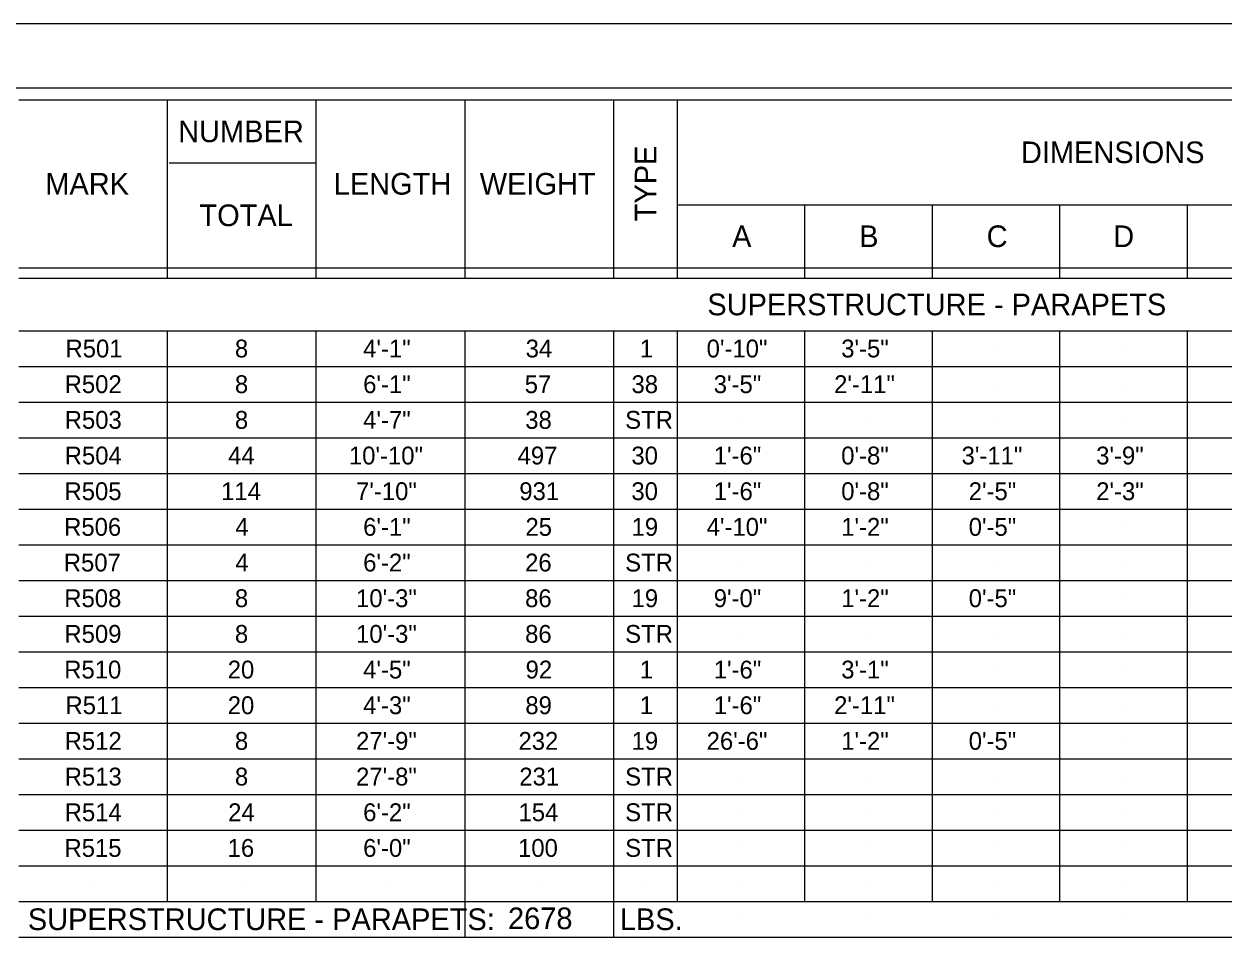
# Model space of a CAD drawing. Extents: x 0 to 34, y 0 to 22.
# Drawn here: x 16.8 to 26.21, y 14.76 to 22 of the extents above; entities that cross this region are included whole.
import ezdxf

# ---------------------------------------------------------------- set-up
doc = ezdxf.new("R2010")
doc.units = 0
for name, color, linetype in [('BR_P_Gen_Text', 7, 'Continuous'), ('SH_Border', 7, 'Continuous'), ('SH_Cut_Line', 7, 'Continuous')]:
    doc.layers.add(name, color=color, linetype=linetype)

msp = doc.modelspace()

# ---------------------------------------------------------------- linework, layer by layer
at = {"layer": 'BR_P_Gen_Text'}
for p, q in [((16.7602, 21.4043), (31.927, 21.4044)), ((17.9269, 20.0043), (17.9269, 21.4043)), ((19.0936, 20.0041), (19.0936, 21.4043)), ((20.2602, 20.0043), (20.2603, 21.4043)), ((21.427, 20.0044), (21.427, 21.4043)), ((21.927, 20.0044), (21.927, 21.4043)), ((17.9406, 20.9102), (19.0936, 20.9102)), ((21.927, 20.5808), (28.927, 20.5809)), ((22.927, 20.0042), (22.927, 20.5808)), ((23.927, 20.0042), (23.927, 20.5808)), ((24.927, 20.0041), (24.927, 20.5809)), ((25.927, 20.0042), (25.927, 20.5809)), ((16.7602, 20.0866), (31.927, 20.0867)), ((16.7602, 20.0043), (31.927, 20.0043)), ((22.8436, 19.7984), (22.8436, 19.7984)), ((16.7602, 19.5926), (31.927, 19.5927)), ((17.9268, 15.1126), (17.9269, 19.5926)), ((19.0936, 15.1126), (19.0936, 19.5926)), ((20.2603, 14.8327), (20.2602, 19.5926)), ((21.427, 14.8327), (21.427, 19.5927)), ((21.927, 15.1126), (21.927, 19.5927)), ((22.9269, 15.1126), (22.927, 19.5926)), ((23.927, 15.1126), (23.927, 19.5926)), ((24.927, 15.1126), (24.927, 19.5926)), ((25.927, 15.1126), (25.927, 19.5926)), ((17.3435, 19.4526), (17.3435, 19.4526)), ((18.5102, 19.4526), (18.5102, 19.4526)), ((19.6769, 19.4526), (19.6769, 19.4526)), ((20.8437, 19.4527), (20.8437, 19.4527)), ((21.677, 19.4526), (21.677, 19.4526)), ((22.427, 19.4526), (22.427, 19.4526)), ((23.427, 19.4526), (23.427, 19.4526)), ((24.427, 19.4526), (24.427, 19.4526)), ((25.427, 19.4526), (25.427, 19.4526)), ((16.7602, 19.3126), (31.927, 19.3126)), ((17.3435, 19.1726), (17.3435, 19.1726)), ((18.5102, 19.1726), (18.5102, 19.1726)), ((19.6769, 19.1726), (19.6769, 19.1726)), ((20.8437, 19.1727), (20.8437, 19.1727)), ((21.677, 19.1726), (21.677, 19.1726)), ((22.427, 19.1726), (22.427, 19.1726)), ((23.427, 19.1726), (23.427, 19.1726)), ((23.427, 19.1726), (23.427, 19.1726)), ((24.427, 19.1726), (24.427, 19.1726)), ((25.427, 19.1726), (25.427, 19.1726)), ((16.7602, 19.0326), (31.927, 19.0326)), ((17.3435, 18.8926), (17.3435, 18.8926)), ((18.5102, 18.8926), (18.5102, 18.8926)), ((19.6769, 18.8926), (19.6769, 18.8926)), ((20.8437, 18.8927), (20.8437, 18.8927)), ((21.677, 18.8926), (21.677, 18.8926)), ((22.427, 18.8926), (22.427, 18.8926)), ((23.427, 18.8926), (23.427, 18.8926)), ((24.427, 18.8926), (24.427, 18.8926)), ((25.427, 18.8926), (25.427, 18.8926)), ((16.7602, 18.7526), (31.927, 18.7526)), ((17.3435, 18.6126), (17.3435, 18.6126)), ((17.3435, 18.6126), (17.3435, 18.6126)), ((22.427, 18.6126), (22.427, 18.6126)), ((23.427, 18.6126), (23.427, 18.6126)), ((24.427, 18.6126), (24.427, 18.6126)), ((25.427, 18.6126), (25.427, 18.6126)), ((16.7602, 18.4726), (31.927, 18.4726)), ((17.3435, 18.3326), (17.3435, 18.3326)), ((18.5102, 18.3326), (18.5102, 18.3326)), ((19.6769, 18.3326), (19.6769, 18.3326)), ((20.8437, 18.3327), (20.8437, 18.3327)), ((21.677, 18.3326), (21.677, 18.3326)), ((22.427, 18.3326), (22.427, 18.3326)), ((23.427, 18.3326), (23.427, 18.3326)), ((24.427, 18.3326), (24.427, 18.3326)), ((25.427, 18.3326), (25.427, 18.3326)), ((16.7602, 18.1926), (31.927, 18.1926)), ((17.3435, 18.0526), (17.3435, 18.0526)), ((18.5102, 18.0526), (18.5102, 18.0526)), ((19.6769, 18.0526), (19.6769, 18.0526)), ((20.8437, 18.0527), (20.8437, 18.0527)), ((21.677, 18.0526), (21.677, 18.0526)), ((22.427, 18.0526), (22.427, 18.0526)), ((23.427, 18.0526), (23.427, 18.0526)), ((24.427, 18.0526), (24.427, 18.0526)), ((25.427, 18.0526), (25.427, 18.0526)), ((16.7602, 17.9126), (31.927, 17.9127)), ((17.3435, 17.7726), (17.3435, 17.7726)), ((18.5102, 17.7726), (18.5102, 17.7726)), ((19.6769, 17.7726), (19.6769, 17.7726)), ((20.8437, 17.7727), (20.8437, 17.7727)), ((21.677, 17.7726), (21.677, 17.7726)), ((22.427, 17.7726), (22.427, 17.7726)), ((23.427, 17.7726), (23.427, 17.7726)), ((24.427, 17.7726), (24.427, 17.7726)), ((25.427, 17.7726), (25.427, 17.7726)), ((16.7602, 17.6326), (31.927, 17.6327)), ((17.3435, 17.4926), (17.3435, 17.4926)), ((17.3435, 17.4926), (17.3435, 17.4926)), ((18.5102, 17.4926), (18.5102, 17.4926)), ((18.5102, 17.4926), (18.5102, 17.4926)), ((19.6769, 17.4926), (19.6769, 17.4926)), ((19.6769, 17.4926), (19.6769, 17.4926)), ((20.8437, 17.4927), (20.8437, 17.4927)), ((20.8437, 17.4927), (20.8437, 17.4927)), ((21.677, 17.4926), (21.677, 17.4926)), ((21.677, 17.4926), (21.677, 17.4926)), ((22.427, 17.4926), (22.427, 17.4926)), ((22.427, 17.4926), (22.427, 17.4926)), ((23.427, 17.4926), (23.427, 17.4926)), ((23.427, 17.4926), (23.427, 17.4926)), ((24.427, 17.4926), (24.427, 17.4926)), ((24.427, 17.4926), (24.427, 17.4926)), ((25.427, 17.4926), (25.427, 17.4926)), ((25.427, 17.4926), (25.427, 17.4926)), ((16.7602, 17.3526), (31.927, 17.3527)), ((17.3435, 17.2126), (17.3435, 17.2126)), ((17.3435, 17.2126), (17.3435, 17.2126)), ((18.5102, 17.2126), (18.5102, 17.2126)), ((18.5102, 17.2126), (18.5102, 17.2126)), ((19.6769, 17.2126), (19.6769, 17.2126)), ((19.6769, 17.2126), (19.6769, 17.2126)), ((20.8437, 17.2127), (20.8437, 17.2127)), ((20.8437, 17.2127), (20.8437, 17.2127)), ((21.677, 17.2126), (21.677, 17.2126)), ((21.677, 17.2126), (21.677, 17.2126)), ((22.427, 17.2126), (22.427, 17.2126)), ((22.427, 17.2126), (22.427, 17.2126)), ((23.427, 17.2126), (23.427, 17.2126)), ((23.427, 17.2126), (23.427, 17.2126)), ((24.427, 17.2126), (24.427, 17.2126)), ((24.427, 17.2126), (24.427, 17.2126)), ((25.427, 17.2126), (25.427, 17.2126)), ((25.427, 17.2126), (25.427, 17.2126)), ((16.7602, 17.0726), (31.927, 17.0727)), ((17.3435, 16.9326), (17.3435, 16.9326)), ((18.5102, 16.9326), (18.5102, 16.9326)), ((19.6769, 16.9326), (19.6769, 16.9326)), ((20.8437, 16.9327), (20.8437, 16.9327)), ((21.677, 16.9326), (21.677, 16.9326)), ((22.427, 16.9326), (22.427, 16.9326)), ((23.427, 16.9326), (23.427, 16.9326)), ((24.427, 16.9326), (24.427, 16.9326)), ((25.427, 16.9326), (25.427, 16.9326)), ((16.7602, 16.7926), (31.927, 16.7926)), ((17.3435, 16.6526), (17.3435, 16.6526)), ((18.5102, 16.6526), (18.5102, 16.6526)), ((19.6769, 16.6526), (19.6769, 16.6526)), ((20.8437, 16.6527), (20.8437, 16.6527)), ((21.677, 16.6526), (21.677, 16.6526)), ((22.427, 16.6526), (22.427, 16.6526)), ((23.427, 16.6526), (23.427, 16.6526)), ((24.427, 16.6526), (24.427, 16.6526)), ((25.427, 16.6526), (25.427, 16.6526)), ((16.7602, 16.5126), (31.927, 16.5126)), ((17.3435, 16.3726), (17.3435, 16.3726)), ((18.5102, 16.3726), (18.5102, 16.3726)), ((19.6769, 16.3726), (19.6769, 16.3726)), ((20.8437, 16.3727), (20.8437, 16.3727)), ((21.677, 16.3726), (21.677, 16.3726)), ((22.427, 16.3726), (22.427, 16.3726)), ((23.427, 16.3726), (23.427, 16.3726)), ((24.427, 16.3726), (24.427, 16.3726)), ((25.427, 16.3726), (25.427, 16.3726)), ((16.7602, 16.2326), (31.927, 16.2326)), ((17.3435, 16.0926), (17.3435, 16.0926)), ((18.5102, 16.0926), (18.5102, 16.0926)), ((19.6769, 16.0926), (19.6769, 16.0926)), ((20.8437, 16.0927), (20.8437, 16.0927)), ((21.677, 16.0926), (21.677, 16.0926)), ((22.427, 16.0926), (22.427, 16.0926)), ((23.427, 16.0926), (23.427, 16.0926)), ((24.427, 16.0926), (24.427, 16.0926)), ((25.427, 16.0926), (25.427, 16.0926)), ((16.7602, 15.9526), (31.927, 15.9526)), ((17.3435, 15.8126), (17.3435, 15.8126)), ((18.5102, 15.8126), (18.5102, 15.8126)), ((19.6769, 15.8126), (19.6769, 15.8126)), ((20.8437, 15.8127), (20.8437, 15.8127)), ((21.677, 15.8126), (21.677, 15.8126)), ((22.427, 15.8126), (22.427, 15.8126)), ((23.427, 15.8126), (23.427, 15.8126)), ((24.427, 15.8126), (24.427, 15.8126)), ((25.427, 15.8126), (25.427, 15.8126)), ((16.7602, 15.6726), (31.927, 15.6726)), ((17.3435, 15.5326), (17.3435, 15.5326)), ((18.5102, 15.5326), (18.5102, 15.5326)), ((19.6769, 15.5326), (19.6769, 15.5326)), ((20.8437, 15.5327), (20.8437, 15.5327)), ((21.677, 15.5326), (21.677, 15.5326)), ((22.427, 15.5326), (22.427, 15.5326)), ((23.427, 15.5326), (23.427, 15.5326)), ((24.427, 15.5326), (24.427, 15.5326)), ((25.427, 15.5326), (25.427, 15.5326)), ((16.7602, 15.3926), (31.927, 15.3926)), ((17.3435, 15.2526), (17.3435, 15.2526)), ((18.5102, 15.2526), (18.5102, 15.2526)), ((19.6769, 15.2526), (19.6769, 15.2526)), ((20.8437, 15.2527), (20.8437, 15.2527)), ((21.677, 15.2526), (21.677, 15.2526)), ((22.427, 15.2526), (22.427, 15.2526)), ((23.427, 15.2526), (23.427, 15.2526)), ((24.427, 15.2526), (24.427, 15.2526)), ((25.427, 15.2526), (25.427, 15.2526)), ((16.7602, 15.1126), (31.927, 15.1126)), ((17.3435, 14.9726), (17.3435, 14.9726)), ((18.5102, 14.9726), (18.5102, 14.9726)), ((19.6769, 14.9726), (19.6769, 14.9726)), ((20.8437, 14.9727), (20.8437, 14.9727)), ((21.677, 14.9726), (21.677, 14.9726)), ((22.427, 14.9726), (22.427, 14.9726)), ((23.427, 14.9726), (23.427, 14.9726)), ((24.427, 14.9726), (24.427, 14.9726)), ((25.427, 14.9726), (25.427, 14.9726)), ((16.7602, 14.8327), (31.927, 14.8327))]:
    msp.add_line(p, q, dxfattribs=at)
at = {"layer": 'SH_Border'}
msp.add_lwpolyline([(1.5, 21.5), (33.5, 21.5), (33.5, 0.5), (1.5, 0.5)], close=True, dxfattribs=at)
at = {"layer": 'SH_Cut_Line'}
msp.add_lwpolyline([(0, 0), (34, 0), (34, 22), (0, 22)], close=True, dxfattribs=at)

# ---------------------------------------------------------------- texts
at = {"layer": 'BR_P_Gen_Text'}
for s, height, p in [('NUMBER', 0.17, (18.0101, 21.0722)), ('DIMENSIONS', 0.17, (24.6212, 20.9076)), ('MARK', 0.17, (16.9678, 20.6605)), ('LENGTH', 0.17, (19.2303, 20.6605)), ('WEIGHT', 0.17, (20.3758, 20.6605)), ('TOTAL', 0.17, (18.1771, 20.4134)), ('A', 0.17, (22.3553, 20.2488)), ('B', 0.17, (23.3522, 20.2488)), ('C', 0.17, (24.3522, 20.2488)), ('D', 0.17, (25.3449, 20.2488)), ('SUPERSTRUCTURE - PARAPETS', 0.17, (22.1609, 19.7135)), ('R501', 0.14, (17.1261, 19.3826)), ('8', 0.14, (18.4552, 19.3826)), ('4\'-1"', 0.14, (19.4613, 19.3826)), ('34', 0.14, (20.7359, 19.3826)), ('1', 0.14, (21.6311, 19.3826)), ('0\'-10"', 0.14, (22.1555, 19.3826)), ('3\'-5"', 0.14, (23.2113, 19.3826)), ('R502', 0.14, (17.1197, 19.1026)), ('8', 0.14, (18.4552, 19.1026)), ('6\'-1"', 0.14, (19.4613, 19.1026)), ('57', 0.14, (20.7287, 19.1026)), ('38', 0.14, (21.5661, 19.1026)), ('3\'-5"', 0.14, (22.2113, 19.1026)), ('2\'-11"', 0.14, (23.1555, 19.1026)), ('R503', 0.14, (17.1201, 18.8226)), ('8', 0.14, (18.4552, 18.8226)), ('4\'-7"', 0.14, (19.4613, 18.8226)), ('38', 0.14, (20.7328, 18.8226)), ('STR', 0.14, (21.5168, 18.8226)), ('R504', 0.14, (17.1201, 18.5426)), ('44', 0.14, (18.4025, 18.5426)), ('10\'-10"', 0.14, (19.3496, 18.5426)), ('497', 0.14, (20.6728, 18.5426)), ('30', 0.14, (21.5655, 18.5426)), ('1\'-6"', 0.14, (22.2113, 18.5426)), ('0\'-8"', 0.14, (23.2113, 18.5426)), ('3\'-11"', 0.14, (24.1555, 18.5426)), ('3\'-9"', 0.14, (25.2113, 18.5426)), ('R505', 0.14, (17.1184, 18.2626)), ('114', 0.14, (18.3466, 18.2626)), ('7\'-10"', 0.14, (19.4055, 18.2626)), ('931', 0.14, (20.6861, 18.2626)), ('30', 0.14, (21.5655, 18.2626)), ('1\'-6"', 0.14, (22.2113, 18.2626)), ('0\'-8"', 0.14, (23.2113, 18.2626)), ('2\'-5"', 0.14, (24.2113, 18.2626)), ('2\'-3"', 0.14, (25.2113, 18.2626)), ('R506', 0.14, (17.1157, 17.9826)), ('4', 0.14, (18.4584, 17.9826)), ('6\'-1"', 0.14, (19.4613, 17.9826)), ('25', 0.14, (20.7343, 17.9826)), ('19', 0.14, (21.5668, 17.9826)), ('4\'-10"', 0.14, (22.1555, 17.9826)), ('1\'-2"', 0.14, (23.2113, 17.9826)), ('0\'-5"', 0.14, (24.2113, 17.9826)), ('R507', 0.14, (17.1128, 17.7026)), ('4', 0.14, (18.4584, 17.7026)), ('6\'-2"', 0.14, (19.4613, 17.7026)), ('26', 0.14, (20.7316, 17.7026)), ('STR', 0.14, (21.5168, 17.7026)), ('R508', 0.14, (17.1169, 17.4226)), ('8', 0.14, (18.4552, 17.4226)), ('10\'-3"', 0.14, (19.4055, 17.4226)), ('86', 0.14, (20.7316, 17.4226)), ('19', 0.14, (21.5668, 17.4226)), ('9\'-0"', 0.14, (22.2113, 17.4226)), ('1\'-2"', 0.14, (23.2113, 17.4226)), ('0\'-5"', 0.14, (24.2113, 17.4226)), ('R509', 0.14, (17.1177, 17.1426)), ('8', 0.14, (18.4552, 17.1426)), ('10\'-3"', 0.14, (19.4055, 17.1426)), ('86', 0.14, (20.7316, 17.1426)), ('STR', 0.14, (21.5168, 17.1426)), ('R510', 0.14, (17.1163, 16.8626)), ('20', 0.14, (18.3988, 16.8626)), ('4\'-5"', 0.14, (19.4613, 16.8626)), ('92', 0.14, (20.7355, 16.8626)), ('1', 0.14, (21.6311, 16.8626)), ('1\'-6"', 0.14, (22.2113, 16.8626)), ('3\'-1"', 0.14, (23.2113, 16.8626)), ('R511', 0.14, (17.1261, 16.5826)), ('20', 0.14, (18.3988, 16.5826)), ('4\'-3"', 0.14, (19.4613, 16.5826)), ('89', 0.14, (20.7335, 16.5826)), ('1', 0.14, (21.6311, 16.5826)), ('1\'-6"', 0.14, (22.2113, 16.5826)), ('2\'-11"', 0.14, (23.1555, 16.5826)), ('R512', 0.14, (17.1197, 16.3026)), ('8', 0.14, (18.4552, 16.3026)), ('27\'-9"', 0.14, (19.4055, 16.3026)), ('232', 0.14, (20.6796, 16.3026)), ('19', 0.14, (21.5668, 16.3026)), ('26\'-6"', 0.14, (22.1555, 16.3026)), ('1\'-2"', 0.14, (23.2113, 16.3026)), ('0\'-5"', 0.14, (24.2113, 16.3026)), ('R513', 0.14, (17.1201, 16.0226)), ('8', 0.14, (18.4552, 16.0226)), ('27\'-8"', 0.14, (19.4055, 16.0226)), ('231', 0.14, (20.6861, 16.0226)), ('STR', 0.14, (21.5168, 16.0226)), ('R514', 0.14, (17.1201, 15.7426)), ('24', 0.14, (18.4025, 15.7426)), ('6\'-2"', 0.14, (19.4613, 15.7426)), ('154', 0.14, (20.68, 15.7426)), ('STR', 0.14, (21.5168, 15.7426)), ('R515', 0.14, (17.1184, 15.4626)), ('16', 0.14, (18.3982, 15.4626)), ('6\'-0"', 0.14, (19.4613, 15.4626)), ('100', 0.14, (20.6763, 15.4626)), ('STR', 0.14, (21.5168, 15.4626)), ('2678', 0.17, (20.5975, 14.895)), ('SUPERSTRUCTURE - PARAPETS:', 0.17, (16.831, 14.8877)), ('LBS.', 0.17, (21.4752, 14.8877))]:
    msp.add_text(s, height=height, dxfattribs=at).set_placement(p)
msp.add_text('TYPE', height=0.17, rotation=90, dxfattribs=at).set_placement((21.762, 20.4517))

doc.saveas('drawing.dxf')
